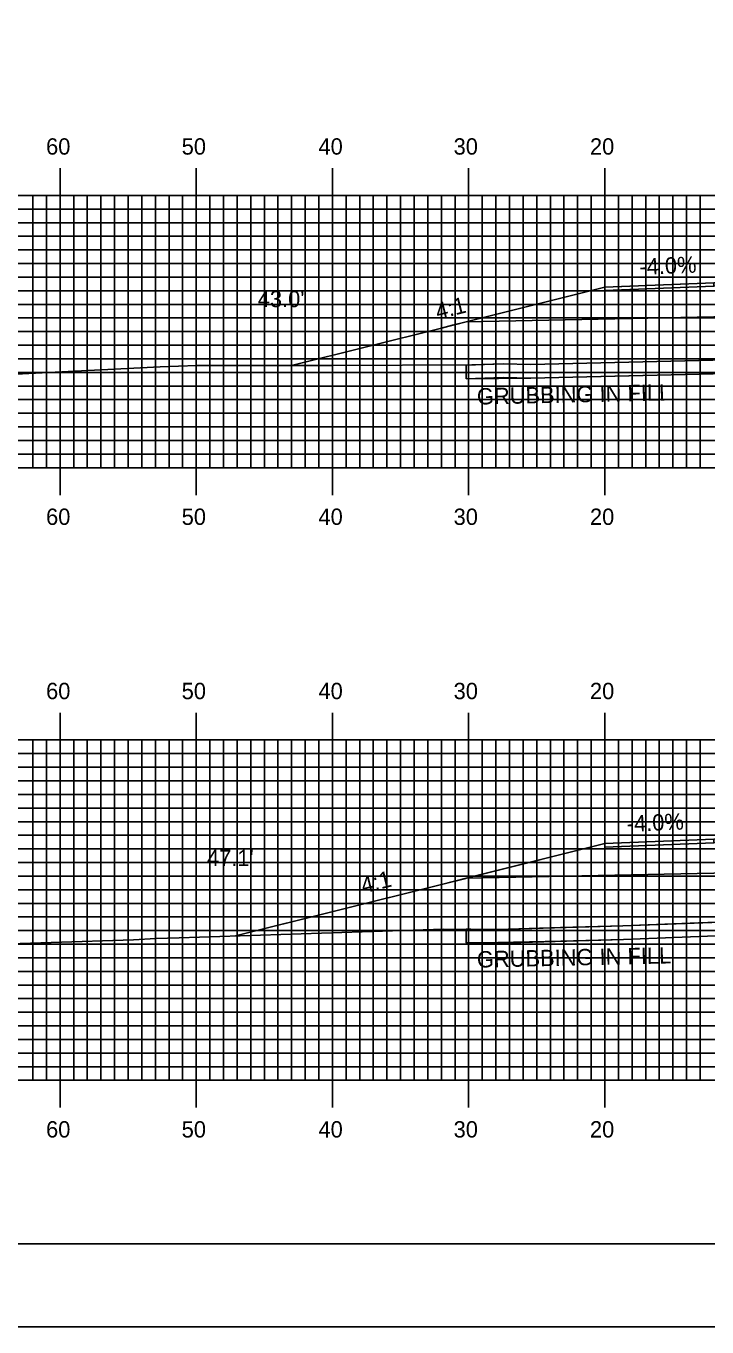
# Model space of a CAD drawing. Extents: x 1777925 to 1778268, y 442591 to 442811.
# Drawn here: x 1778028.3 to 1778078.3, y 442590.5 to 442686.1 of the extents above; entities that cross this region are included whole.
import ezdxf

# ---------------------------------------------------------------- set-up
doc = ezdxf.new("R2010")
doc.units = 0
for name, color, linetype in [('ANNOTATION', 7, 'Continuous'), ('BORDER', 7, 'Continuous'), ('D_Roadway_Centerline', 7, 'Continuous'), ('D_Roadway_Edge_Shoulder', 7, 'Continuous'), ('D_Roadway_SlopeLines', 7, 'Continuous'), ('D_Roadway_SubGrade', 7, 'Continuous'), ('D_Text_Standard', 7, 'Continuous'), ('GRUBBING IN FILL', 7, 'Continuous'), ('H_V ANNOTATION', 7, 'Continuous'), ('MAJOR', 7, 'Continuous'), ('MINOR', 7, 'Continuous'), ('PLOT BOUNDARY', 7, 'Continuous'), ('S_Roadway_Centerline', 7, 'Continuous')]:
    doc.layers.add(name, color=color, linetype=linetype)

msp = doc.modelspace()

# ---------------------------------------------------------------- linework, layer by layer
at = {"layer": 'BORDER'}
msp.add_lwpolyline([(1777941.19, 442596.665), (1778261.19, 442596.665), (1778261.19, 442806.665), (1777941.19, 442806.665)], close=True, dxfattribs=at)
at = {"layer": 'D_Roadway_Centerline'}
for points in [[(1778047.792, 442661.178), (1778058.79, 442663.927), (1778059.609, 442664.132), (1778060.616, 442664.384), (1778070.79, 442666.927), (1778072.648, 442667.002), (1778078.79, 442667.247), (1778085.551, 442667.382), (1778090.79, 442667.487), (1778102.79, 442667.247), (1778110.79, 442666.927), (1778115.943, 442665.639), (1778120.963, 442664.384), (1778121.24, 442664.315), (1778127.328, 442662.793)], [(1778043.66, 442619.27), (1778050.556, 442620.994), (1778058.789, 442623.052), (1778058.79, 442623.052), (1778060.591, 442623.503), (1778060.617, 442623.509), (1778061.603, 442623.756), (1778070.79, 442626.052), (1778078.79, 442626.372), (1778090.79, 442626.612), (1778096.258, 442626.503), (1778102.79, 442626.372), (1778108.725, 442626.135), (1778110.79, 442626.052), (1778120.964, 442623.509), (1778126.145, 442622.214), (1778131.883, 442620.779)]]:
    msp.add_lwpolyline(points, dxfattribs=at)
at = {"layer": 'D_Roadway_Edge_Shoulder'}
for points in [[(1778078.79, 442667.247), (1778070.79, 442666.927), (1778070.79, 442666.677), (1778078.79, 442666.997)], [(1778078.79, 442626.372), (1778070.79, 442626.052), (1778070.79, 442625.802), (1778078.79, 442626.122)]]:
    msp.add_lwpolyline(points, close=True, dxfattribs=at)
at = {"layer": 'D_Roadway_SlopeLines'}
for points in [[(1778070.79, 442666.927), (1778060.616, 442664.384), (1778058.79, 442663.927), (1778047.792, 442661.178)], [(1778070.79, 442626.052), (1778060.617, 442623.509), (1778058.79, 442623.052), (1778043.66, 442619.27)]]:
    msp.add_lwpolyline(points, dxfattribs=at)
at = {"layer": 'D_Roadway_SubGrade'}
for points in [[(1778078.79, 442664.747), (1778060.616, 442664.384), (1778070.79, 442666.927), (1778070.79, 442666.677), (1778078.79, 442666.997), (1778090.79, 442667.237), (1778102.79, 442666.997), (1778110.79, 442666.677), (1778110.79, 442666.927), (1778120.963, 442664.384), (1778102.79, 442664.747), (1778090.79, 442664.987)], [(1778078.79, 442623.872), (1778060.617, 442623.509), (1778070.79, 442626.052), (1778070.79, 442625.802), (1778078.79, 442626.122), (1778090.79, 442626.362), (1778102.79, 442626.122), (1778110.79, 442625.802), (1778110.79, 442626.052), (1778120.964, 442623.509), (1778102.79, 442623.872), (1778090.79, 442624.112)]]:
    msp.add_lwpolyline(points, close=True, dxfattribs=at)
at = {"layer": 'GRUBBING IN FILL'}
for p, q in [((1778060.616, 442660.205), (1778060.616, 442661.205)), ((1778060.616, 442660.205), (1778060.616, 442661.205)), ((1778060.617, 442619.76), (1778060.617, 442618.76)), ((1778060.617, 442619.76), (1778060.617, 442618.76))]:
    msp.add_line(p, q, dxfattribs=at)
for points in [[(1778060.616, 442661.205), (1778063.326, 442661.288), (1778065.358, 442661.247), (1778074.613, 442661.472), (1778083.869, 442661.697), (1778090.79, 442661.86), (1778090.79, 442660.86), (1778083.893, 442660.697), (1778074.626, 442660.472), (1778065.36, 442660.247), (1778060.616, 442660.205)], [(1778060.616, 442661.205), (1778063.326, 442661.288), (1778065.358, 442661.247), (1778074.613, 442661.472), (1778083.869, 442661.697), (1778090.79, 442661.86), (1778090.79, 442660.86), (1778083.893, 442660.697), (1778074.626, 442660.472), (1778065.36, 442660.247), (1778060.616, 442660.205)], [(1778060.617, 442619.76), (1778060.942, 442619.759), (1778062.934, 442619.752), (1778067.528, 442619.88), (1778072.121, 442620.007), (1778077.667, 442620.223), (1778083.213, 442620.439), (1778086.468, 442620.6), (1778089.507, 442620.579), (1778090.27, 442620.574), (1778090.79, 442620.57), (1778090.79, 442619.57), (1778086.492, 442619.6), (1778085.99, 442619.572), (1778083.256, 442619.44), (1778072.155, 442619.007), (1778067.551, 442618.88), (1778061.781, 442618.756), (1778060.617, 442618.76)], [(1778060.617, 442619.76), (1778060.942, 442619.759), (1778062.934, 442619.752), (1778067.528, 442619.88), (1778072.121, 442620.007), (1778077.667, 442620.223), (1778083.213, 442620.439), (1778086.468, 442620.6), (1778089.507, 442620.579), (1778090.27, 442620.574), (1778090.79, 442620.57), (1778090.79, 442619.57), (1778086.492, 442619.6), (1778085.99, 442619.572), (1778083.256, 442619.44), (1778072.155, 442619.007), (1778067.551, 442618.88), (1778061.781, 442618.756), (1778060.617, 442618.76)]]:
    msp.add_lwpolyline(points, close=True, dxfattribs=at)
for points in [[(1778060.616, 442660.205), (1778063.331, 442660.288), (1778065.36, 442660.247), (1778083.893, 442660.697), (1778097.822, 442661.026), (1778107.179, 442660.909), (1778109.141, 442660.925), (1778111.271, 442661.052), (1778120.963, 442661.499)], [(1778060.616, 442660.205), (1778063.331, 442660.288), (1778065.36, 442660.247), (1778083.893, 442660.697), (1778097.822, 442661.026), (1778107.179, 442660.909), (1778109.141, 442660.925), (1778111.271, 442661.052), (1778120.963, 442661.499)], [(1778060.617, 442618.76), (1778062.946, 442618.752), (1778072.155, 442619.007), (1778083.256, 442619.44), (1778085.488, 442619.545), (1778086.492, 442619.6), (1778107.624, 442619.454), (1778108.339, 442619.459), (1778120.964, 442619.638)], [(1778060.617, 442618.76), (1778062.946, 442618.752), (1778072.155, 442619.007), (1778083.256, 442619.44), (1778085.488, 442619.545), (1778086.492, 442619.6), (1778107.624, 442619.454), (1778108.339, 442619.459), (1778120.964, 442619.638)]]:
    msp.add_lwpolyline(points, dxfattribs=at)
at = {"layer": 'MAJOR'}
for p, q in [((1778030.79, 442675.669), (1778030.79, 442673.665)), ((1778040.79, 442675.669), (1778040.79, 442673.665)), ((1778050.79, 442675.669), (1778050.79, 442673.665)), ((1778060.79, 442675.669), (1778060.79, 442673.665)), ((1778070.79, 442675.669), (1778070.79, 442673.665)), ((1777950.79, 442673.665), (1778230.79, 442673.665)), ((1777950.79, 442673.665), (1778230.79, 442673.665)), ((1778030.79, 442653.665), (1778030.79, 442673.665)), ((1778040.79, 442653.665), (1778040.79, 442673.665)), ((1778050.79, 442653.665), (1778050.79, 442673.665)), ((1778060.79, 442653.665), (1778060.79, 442673.665)), ((1778070.79, 442653.665), (1778070.79, 442673.665)), ((1777950.79, 442668.665), (1778230.79, 442668.665)), ((1777950.79, 442663.665), (1778230.79, 442663.665)), ((1777950.79, 442658.665), (1778230.79, 442658.665)), ((1777950.79, 442653.665), (1778230.79, 442653.665)), ((1777950.79, 442653.665), (1778230.79, 442653.665)), ((1778030.79, 442651.661), (1778030.79, 442653.665)), ((1778040.79, 442651.661), (1778040.79, 442653.665)), ((1778050.79, 442651.661), (1778050.79, 442653.665)), ((1778060.79, 442651.661), (1778060.79, 442653.665)), ((1778070.79, 442651.661), (1778070.79, 442653.665)), ((1778030.79, 442635.669), (1778030.79, 442633.665)), ((1778040.79, 442635.669), (1778040.79, 442633.665)), ((1778050.79, 442635.669), (1778050.79, 442633.665)), ((1778060.79, 442635.669), (1778060.79, 442633.665)), ((1778070.79, 442635.669), (1778070.79, 442633.665)), ((1777950.79, 442633.665), (1778230.79, 442633.665)), ((1777950.79, 442633.665), (1778230.79, 442633.665)), ((1778030.79, 442608.665), (1778030.79, 442633.665)), ((1778040.79, 442608.665), (1778040.79, 442633.665)), ((1778050.79, 442608.665), (1778050.79, 442633.665)), ((1778060.79, 442608.665), (1778060.79, 442633.665)), ((1778070.79, 442608.665), (1778070.79, 442633.665)), ((1777950.79, 442628.665), (1778230.79, 442628.665)), ((1777950.79, 442623.665), (1778230.79, 442623.665)), ((1777950.79, 442618.665), (1778230.79, 442618.665)), ((1777950.79, 442613.665), (1778230.79, 442613.665)), ((1777950.79, 442608.665), (1778230.79, 442608.665)), ((1777950.79, 442608.665), (1778230.79, 442608.665)), ((1778030.79, 442606.661), (1778030.79, 442608.665)), ((1778040.79, 442606.661), (1778040.79, 442608.665)), ((1778050.79, 442606.661), (1778050.79, 442608.665)), ((1778060.79, 442606.661), (1778060.79, 442608.665)), ((1778070.79, 442606.661), (1778070.79, 442608.665))]:
    msp.add_line(p, q, dxfattribs=at)
at = {"layer": 'MINOR'}
for p, q in [((1778028.79, 442653.665), (1778028.79, 442673.665)), ((1778029.79, 442653.665), (1778029.79, 442673.665)), ((1778031.79, 442653.665), (1778031.79, 442673.665)), ((1778032.79, 442653.665), (1778032.79, 442673.665)), ((1778033.79, 442653.665), (1778033.79, 442673.665)), ((1778034.79, 442653.665), (1778034.79, 442673.665)), ((1778035.79, 442653.665), (1778035.79, 442673.665)), ((1778036.79, 442653.665), (1778036.79, 442673.665)), ((1778037.79, 442653.665), (1778037.79, 442673.665)), ((1778038.79, 442653.665), (1778038.79, 442673.665)), ((1778039.79, 442653.665), (1778039.79, 442673.665)), ((1778041.79, 442653.665), (1778041.79, 442673.665)), ((1778042.79, 442653.665), (1778042.79, 442673.665)), ((1778043.79, 442653.665), (1778043.79, 442673.665)), ((1778044.79, 442653.665), (1778044.79, 442673.665)), ((1778045.79, 442653.665), (1778045.79, 442673.665)), ((1778046.79, 442653.665), (1778046.79, 442673.665)), ((1778047.79, 442653.665), (1778047.79, 442673.665)), ((1778048.79, 442653.665), (1778048.79, 442673.665)), ((1778049.79, 442653.665), (1778049.79, 442673.665)), ((1778051.79, 442653.665), (1778051.79, 442673.665)), ((1778052.79, 442653.665), (1778052.79, 442673.665)), ((1778053.79, 442653.665), (1778053.79, 442673.665)), ((1778054.79, 442653.665), (1778054.79, 442673.665)), ((1778055.79, 442653.665), (1778055.79, 442673.665)), ((1778056.79, 442653.665), (1778056.79, 442673.665)), ((1778057.79, 442653.665), (1778057.79, 442673.665)), ((1778058.79, 442653.665), (1778058.79, 442673.665)), ((1778059.79, 442653.665), (1778059.79, 442673.665)), ((1778061.79, 442653.665), (1778061.79, 442673.665)), ((1778062.79, 442653.665), (1778062.79, 442673.665)), ((1778063.79, 442653.665), (1778063.79, 442673.665)), ((1778064.79, 442653.665), (1778064.79, 442673.665)), ((1778065.79, 442653.665), (1778065.79, 442673.665)), ((1778066.79, 442653.665), (1778066.79, 442673.665)), ((1778067.79, 442653.665), (1778067.79, 442673.665)), ((1778068.79, 442653.665), (1778068.79, 442673.665)), ((1778069.79, 442653.665), (1778069.79, 442673.665)), ((1778071.79, 442653.665), (1778071.79, 442673.665)), ((1778072.79, 442653.665), (1778072.79, 442673.665)), ((1778073.79, 442653.665), (1778073.79, 442673.665)), ((1778074.79, 442653.665), (1778074.79, 442673.665)), ((1778075.79, 442653.665), (1778075.79, 442673.665)), ((1778076.79, 442653.665), (1778076.79, 442673.665)), ((1778077.79, 442653.665), (1778077.79, 442673.665)), ((1777950.79, 442672.665), (1778230.79, 442672.665)), ((1777950.79, 442671.665), (1778230.79, 442671.665)), ((1777950.79, 442670.665), (1778230.79, 442670.665)), ((1777950.79, 442669.665), (1778230.79, 442669.665)), ((1777950.79, 442667.665), (1778230.79, 442667.665)), ((1777950.79, 442666.665), (1778230.79, 442666.665)), ((1777950.79, 442665.665), (1778230.79, 442665.665)), ((1777950.79, 442664.665), (1778230.79, 442664.665)), ((1777950.79, 442662.665), (1778230.79, 442662.665)), ((1777950.79, 442661.665), (1778230.79, 442661.665)), ((1777950.79, 442660.665), (1778230.79, 442660.665)), ((1777950.79, 442659.665), (1778230.79, 442659.665)), ((1777950.79, 442657.665), (1778230.79, 442657.665)), ((1777950.79, 442656.665), (1778230.79, 442656.665)), ((1777950.79, 442655.665), (1778230.79, 442655.665)), ((1777950.79, 442654.665), (1778230.79, 442654.665)), ((1778028.79, 442608.665), (1778028.79, 442633.665)), ((1778029.79, 442608.665), (1778029.79, 442633.665)), ((1778031.79, 442608.665), (1778031.79, 442633.665)), ((1778032.79, 442608.665), (1778032.79, 442633.665)), ((1778033.79, 442608.665), (1778033.79, 442633.665)), ((1778034.79, 442608.665), (1778034.79, 442633.665)), ((1778035.79, 442608.665), (1778035.79, 442633.665)), ((1778036.79, 442608.665), (1778036.79, 442633.665)), ((1778037.79, 442608.665), (1778037.79, 442633.665)), ((1778038.79, 442608.665), (1778038.79, 442633.665)), ((1778039.79, 442608.665), (1778039.79, 442633.665)), ((1778041.79, 442608.665), (1778041.79, 442633.665)), ((1778042.79, 442608.665), (1778042.79, 442633.665)), ((1778043.79, 442608.665), (1778043.79, 442633.665)), ((1778044.79, 442608.665), (1778044.79, 442633.665)), ((1778045.79, 442608.665), (1778045.79, 442633.665)), ((1778046.79, 442608.665), (1778046.79, 442633.665)), ((1778047.79, 442608.665), (1778047.79, 442633.665)), ((1778048.79, 442608.665), (1778048.79, 442633.665)), ((1778049.79, 442608.665), (1778049.79, 442633.665)), ((1778051.79, 442608.665), (1778051.79, 442633.665)), ((1778052.79, 442608.665), (1778052.79, 442633.665)), ((1778053.79, 442608.665), (1778053.79, 442633.665)), ((1778054.79, 442608.665), (1778054.79, 442633.665)), ((1778055.79, 442608.665), (1778055.79, 442633.665)), ((1778056.79, 442608.665), (1778056.79, 442633.665)), ((1778057.79, 442608.665), (1778057.79, 442633.665)), ((1778058.79, 442608.665), (1778058.79, 442633.665)), ((1778059.79, 442608.665), (1778059.79, 442633.665)), ((1778061.79, 442608.665), (1778061.79, 442633.665)), ((1778062.79, 442608.665), (1778062.79, 442633.665)), ((1778063.79, 442608.665), (1778063.79, 442633.665)), ((1778064.79, 442608.665), (1778064.79, 442633.665)), ((1778065.79, 442608.665), (1778065.79, 442633.665)), ((1778066.79, 442608.665), (1778066.79, 442633.665)), ((1778067.79, 442608.665), (1778067.79, 442633.665)), ((1778068.79, 442608.665), (1778068.79, 442633.665)), ((1778069.79, 442608.665), (1778069.79, 442633.665)), ((1778071.79, 442608.665), (1778071.79, 442633.665)), ((1778072.79, 442608.665), (1778072.79, 442633.665)), ((1778073.79, 442608.665), (1778073.79, 442633.665)), ((1778074.79, 442608.665), (1778074.79, 442633.665)), ((1778075.79, 442608.665), (1778075.79, 442633.665)), ((1778076.79, 442608.665), (1778076.79, 442633.665)), ((1778077.79, 442608.665), (1778077.79, 442633.665)), ((1777950.79, 442632.665), (1778230.79, 442632.665)), ((1777950.79, 442631.665), (1778230.79, 442631.665)), ((1777950.79, 442630.665), (1778230.79, 442630.665)), ((1777950.79, 442629.665), (1778230.79, 442629.665)), ((1777950.79, 442627.665), (1778230.79, 442627.665)), ((1777950.79, 442626.665), (1778230.79, 442626.665)), ((1777950.79, 442625.665), (1778230.79, 442625.665)), ((1777950.79, 442624.665), (1778230.79, 442624.665)), ((1777950.79, 442622.665), (1778230.79, 442622.665)), ((1777950.79, 442621.665), (1778230.79, 442621.665)), ((1777950.79, 442620.665), (1778230.79, 442620.665)), ((1777950.79, 442619.665), (1778230.79, 442619.665)), ((1777950.79, 442617.665), (1778230.79, 442617.665)), ((1777950.79, 442616.665), (1778230.79, 442616.665)), ((1777950.79, 442615.665), (1778230.79, 442615.665)), ((1777950.79, 442614.665), (1778230.79, 442614.665)), ((1777950.79, 442612.665), (1778230.79, 442612.665)), ((1777950.79, 442611.665), (1778230.79, 442611.665)), ((1777950.79, 442610.665), (1778230.79, 442610.665)), ((1777950.79, 442609.665), (1778230.79, 442609.665))]:
    msp.add_line(p, q, dxfattribs=at)
at = {"layer": 'PLOT BOUNDARY'}
msp.add_lwpolyline([(1777925.003, 442590.547), (1778265.003, 442590.547), (1778265.003, 442810.547), (1777925.003, 442810.547)], close=True, dxfattribs=at)
at = {"layer": 'S_Roadway_Centerline'}
for points in [[(1777950.79, 442659.341), (1777957.637, 442659.573), (1777969.437, 442659.353), (1777970.922, 442659.383), (1777992.887, 442659.856), (1778004.185, 442659.95), (1778017.022, 442660.194), (1778027.551, 442660.534), (1778038.131, 442661.083), (1778040.821, 442661.181), (1778050.827, 442661.177), (1778061.024, 442661.218), (1778063.326, 442661.288), (1778065.358, 442661.247), (1778083.869, 442661.697), (1778097.817, 442662.026), (1778107.182, 442661.909), (1778109.107, 442661.925), (1778111.218, 442662.05), (1778128.394, 442662.842), (1778134.182, 442662.79)], [(1777950.79, 442617.395), (1777956.017, 442617.414), (1777972.056, 442617.846), (1777979.693, 442617.903), (1777987.767, 442618.089), (1777991.687, 442618.08), (1777995.058, 442618.124), (1778011.222, 442618.225), (1778018.028, 442618.392), (1778036.183, 442618.991), (1778037.813, 442619.081), (1778039.538, 442619.137), (1778058.95, 442619.765), (1778062.934, 442619.752), (1778072.121, 442620.007), (1778083.213, 442620.439), (1778085.437, 442620.544), (1778086.468, 442620.6), (1778107.624, 442620.454), (1778108.328, 442620.459), (1778129.191, 442620.755), (1778131.694, 442620.772), (1778142.049, 442621.162)]]:
    msp.add_lwpolyline(points, dxfattribs=at)

# ---------------------------------------------------------------- texts
at = {"layer": 'ANNOTATION'}
for s, rotation, p in [('-4.0%', 2.29073, (1778073.351, 442667.831)), ('4:1', 14.0329, (1778058.523, 442664.543)), ('-4.0%', 2.29053, (1778072.422, 442626.919)), ('4:1', 14.03477, (1778053.053, 442622.385))]:
    msp.add_text(s, height=1.2, rotation=rotation, dxfattribs=at).set_placement(p)
at = {"layer": 'D_Text_Standard'}
for s, p in [("43.0'", (1778045.305, 442665.463)), ("47.1'", (1778041.578, 442624.398))]:
    msp.add_text(s, height=1.2, dxfattribs=at).set_placement(p)
at = {"layer": 'GRUBBING IN FILL'}
for p in [(1778061.411, 442658.303), (1778061.411, 442616.944)]:
    msp.add_text('GRUBBING IN FILL', height=1.2, rotation=1.25379, dxfattribs=at).set_placement(p)
at = {"layer": 'H_V ANNOTATION'}
for s, p in [('60', (1778029.762, 442676.665)), ('50', (1778039.719, 442676.665)), ('40', (1778049.762, 442676.665)), ('30', (1778059.687, 442676.665)), ('20', (1778069.698, 442676.665)), ('60', (1778029.762, 442649.465)), ('50', (1778039.719, 442649.465)), ('40', (1778049.762, 442649.465)), ('30', (1778059.687, 442649.465)), ('20', (1778069.698, 442649.465)), ('60', (1778029.762, 442636.665)), ('50', (1778039.719, 442636.665)), ('40', (1778049.762, 442636.665)), ('30', (1778059.687, 442636.665)), ('20', (1778069.698, 442636.665)), ('60', (1778029.762, 442604.465)), ('50', (1778039.719, 442604.465)), ('40', (1778049.762, 442604.465)), ('30', (1778059.687, 442604.465)), ('20', (1778069.698, 442604.465))]:
    msp.add_text(s, height=1.2, dxfattribs=at).set_placement(p)

doc.saveas('drawing.dxf')
